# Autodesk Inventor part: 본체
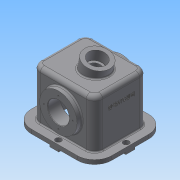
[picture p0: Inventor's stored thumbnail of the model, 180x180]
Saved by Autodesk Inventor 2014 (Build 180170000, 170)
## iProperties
Created: 2014-11
Part Number: 본체
Material: 일반
Document SubType Name: Modeling
Designer: user
Density: 1 g/cm^3
Appearance: 기본값
Author: user
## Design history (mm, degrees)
sketch "스케치1"
  geometry: L1 (-98, 87)-(98, 87); L2 (98, 87)-(98, -87); L3 (98, -87)-(-98, -87); L4 (-98, -87)-(-98, 87); 3 further points
  constraints: 8 end point, 2 midpoint, 2 parallel, 1 horizontal, 1 horizontal alignment, 1 perpendicular, 1 vertical alignment
  dimensions: "d0" = 174 distance of L1.end L2.end; "d1" = 196 distance of L1.start L1.end
extrude "돌출1" new body sketch "스케치1" distance "d2" = 10; taper "d3" = 0 deg
sketch "스케치2"
  geometry: L1 (-76, 65)-(76, 65); L2 (76, 65)-(76, -65); L3 (76, -65)-(-76, -65); L4 (-76, -65)-(-76, 65); 3 further points
  constraints: 8 end point, 2 midpoint, 2 parallel, 1 horizontal, 1 horizontal alignment, 1 perpendicular, 1 vertical alignment
  dimensions: "d4" = 152 distance of L1.start L1.end; "d5" = 130 distance of L1.end L2.end
extrude "돌출2" join sketch "스케치2" distance "d6" = 118; taper "d7" = 0 deg
sketch "스케치4"
  geometry: L1 (-66, 55)-(66, 55); L2 (66, 55)-(66, -55); L3 (66, -55)-(-66, -55); L4 (-66, -55)-(-66, 55); 3 further points
  constraints: 8 end point, 2 midpoint, 2 parallel, 1 horizontal, 1 horizontal alignment, 1 perpendicular, 1 vertical alignment
  dimensions: "d8" = 132 distance of L1.start L1.end; "d9" = 110 distance of L1.end L2.end
extrude "돌출3" cut sketch "스케치4" distance "d10" = 118; taper "d11" = 0 deg
sketch "스케치5"
  geometry: L1 (174, -10)-(-22, -10) reference; C1 r 45.5 at (76, 58); 2 further points
  constraints: 1 centre point, 1 midpoint, 1 vertical alignment
  dimensions: "d12" = 68 distance from line of L1 C1.centre; "d13" = 91 diameter of C1
extrude "돌출4" join sketch "스케치5" distance "d14" = 12; taper "d15" = 0 deg
sketch "스케치6"
  geometry: L1 (113.5, 77)-(22.5, 77) reference; L2 (10, 65)-(128, 65) reference; L3 (68, 77)-(68, 45); L4 (113.5, 77)-(113.5, 55); L5 (113.5, 55)-(103.5, 45); L6 (103.5, 45)-(68, 45); 1 further point
  constraints: 8 end point, 3 perpendicular, 1 midpoint
  dimensions: "d16" = 32 distance of L3.start L3.end; "d17" = 22 distance of L1.start L4.end; "d18" = 71 diameter of L5.end L3
revolve "회전1" sketch "스케치6" stored, may be unused: angle "d19" = 90 deg
sketch "스케치7"
  geometry: L1 (-66, 118)-(66, 118) reference; L2 (0, 68)-(17.88, 152.121); L3 (-76, 128)-(76, 128) reference; L4 (-30.323, 74.445)-(-12.442, 158.566); L5 (-12.442, 158.566)-(17.88, 152.121); L6 (0, 68)-(-30.323, 74.445); C1 r 45.5 at (0, 68) reference; 1 further point
  constraints: 8 end point, 2 perpendicular, 1 parallel
  dimensions: "d20" = 86 distance of L2.start L2.end; "d21" = 78 deg angle of L3 L2; "d22" = 31 distance between parallel lines of L2 L4
revolve "회전2" sketch "스케치7" stored, may be unused: angle "d24" = 90 deg
sketch "스케치8"
  geometry: L1 (-45, 35)-(45, 35); L2 (45, 35)-(45, -35); L3 (45, -35)-(-45, -35); L4 (-45, -35)-(-45, 35); 3 further points
  constraints: 8 end point, 2 midpoint, 2 parallel, 1 horizontal, 1 horizontal alignment, 1 perpendicular, 1 vertical alignment
  dimensions: "d25" = 90 distance of L1.start L1.end; "d26" = 70 distance of L1.end L2.end
extrude "돌출5" cut sketch "스케치8" distance "d27" = 118; taper "d28" = 0 deg
sketch "스케치9"
  geometry: C1 r 31 at (0, 0) reference; C2 r 21 at (0, 0); 1 further point
  constraints: 1 centre point, 1 coincident
  dimensions: "d29" = 42 diameter of C2
extrude "돌출6" cut sketch "스케치9" distance "d30" = 25; taper "d31" = 0 deg
sketch "스케치10"
  geometry: C1 r 21 at (0, 0) reference; C2 r 15 at (0, 0); 1 further point
  constraints: 1 centre point, 1 coincident
  dimensions: "d32" = 30 diameter of C2
extrude "돌출7" cut sketch "스케치10" stored distance "d33" = 25; taper "d34" = 0 deg
sketch "스케치11"
  geometry: L1 (-98, 11)-(-78, 11); L2 (-78, 11)-(-78, -11); L3 (-78, -11)-(-98, -11); L4 (-98, -11)-(-98, 11); L5 (78, 11)-(98, 11); L6 (98, 11)-(98, -11); L7 (98, -11)-(78, -11); L8 (78, -11)-(78, 11); L9 (-11, 87)-(11, 87); L10 (11, 87)-(11, 67); L11 (11, 67)-(-11, 67); L12 (-11, 67)-(-11, 87); L13 (-11, -67)-(11, -67); L14 (11, -67)-(11, -87); L15 (11, -87)-(-11, -87); L16 (-11, -87)-(-11, -67); L17 (98, 87)-(-98, 87) reference; L18 (-98, -87)-(98, -87) reference; L19 (-98, 87)-(-98, -87) reference; L20 (98, -87)-(98, 87) reference; 13 further points
  constraints: 32 end point, 16 midpoint, 8 parallel, 4 coincident, 4 horizontal, 4 perpendicular
  dimensions: "d35" = 22 distance of L1.end L2.end; "d36" = 22 distance of L13.start L13.end; "d37" = 22 distance of L7.end L5.start; "d38" = 22 distance of L10.end L11.end; "d39" = 20 distance of L9.end L10.end; "d40" = 20 distance of L5.start L5.end; "d41" = 20 distance of L1.start L1.end; "d42" = 20 distance of L13.end L14.end
extrude "돌출8" join sketch "스케치11" distance "d43" = 5; taper "d44" = 0 deg
sketch "스케치13"
  geometry: L1 (11, 87)-(-11, 87) reference; L2 (98, -11)-(98, 11) reference; L3 (-11, -87)-(11, -87) reference; L4 (-98, 11)-(-98, -11) reference; C1 r 4.5 at (0, 77); C2 r 4.5 at (88, 0); C3 r 4.5 at (0, -77); C4 r 4.5 at (-88, 0); 1 further point
  constraints: 4 centre point, 3 equal radius, 2 horizontal alignment, 2 vertical alignment
  dimensions: "d45" = 9 diameter of C1; "d46" = 10 distance from line of L1 C1.centre; "d47" = 10 distance from line of L2 C2.centre; "d48" = 10 distance from line of L3 C3.centre; "d49" = 10 distance from line of L4 C4.centre
extrude "돌출9" cut sketch "스케치13" distance "d50" = 6.4; taper "d51" = 0 deg
sketch "스케치15"
  geometry: L1 (45.5, 0)-(-45.5, 0) reference; C1 r 4.5 at (0, 0) reference; C2 r 4.5 at (88, -77) reference; C3 r 4.5 at (0, -154) reference; C4 r 4.5 at (-88, -77) reference; C5 r 7 at (0, 0); C6 r 7 at (88, -77); C7 r 7 at (0, -154); C8 r 7 at (-88, -77); 1 further point
  constraints: 4 centre point, 4 coincident
  dimensions: "d54" = 14 diameter of C5; "d55" = 14 diameter of C6; "d56" = 14 diameter of C7; "d57" = 14 diameter of C8
extrude "돌출10" cut sketch "스케치15" distance "d58" = 8.6; taper "d59" = 0 deg
sketch "스케치16"
  geometry: C1 r 45.5 at (0, 0) reference; C2 r 26 at (0, 0); 1 further point
  constraints: 1 centre point, 1 coincident
  dimensions: "d60" = 52 diameter of C2
extrude "돌출11" cut sketch "스케치16" stored distance "d61" = 8.6; taper "d62" = 0 deg
sketch "스케치17"
  geometry: C1 r 26 at (0, 0) reference; C2 r 45.5 at (0, 0) reference; 5 further points
  constraints: 4 other
hole "구멍1" sketch "스케치17" at (0, 35), (35, 0), (-35, 0), (0, -35) diameter "d64" = 3.242; stored, may be unused: countersink angle "d68" = 82 deg, drill point angle "d70" = 118 deg; dims "d65" = 13, "d66" = 3.023, "d67" = 2, "d69" = 16
sketch "스케치18"
  geometry: L1 (24.943, 87.482)-(105.057, 87.482); L2 (105.057, 87.482)-(105.057, 76.518); L3 (105.057, 76.518)-(24.943, 76.518); L4 (24.943, 76.518)-(24.943, 87.482); L5 (0, 118)-(130, 118) reference; L6 (152, -10)-(76, -10) reference; 3 further points
  constraints: 2 midpoint, 1 vertical alignment, 2 other
extrude "돌출12" join sketch "스케치18" distance "d72" = 1; taper "d73" = 0 deg
chamfer "모따기1" distance "d74" = 1; stored, may be unused: second distance "d75" = 2, angle "d76" = 45 deg
fillet "모깎기1" dims "d77" = 0.3
fillet "모깎기2" dims "d78" = 10
fillet "모깎기3" dims "d79" = 20
fillet "모깎기4" dims "d80" = 42
fillet "모깎기5" dims "d81" = 10
fillet "모깎기6" dims "d82" = 3
node "솔리드1"
mirror "대칭1"
mirror "대칭2"
mirror "대칭3"
node "투영된 루프1"
node "투영된 루프2"
node "투영된 루프3"
node "투영된 루프4"
node "투영된 루프5"
node "투영된 루프6"
node "투영된 루프7"
node "투영된 루프8"
